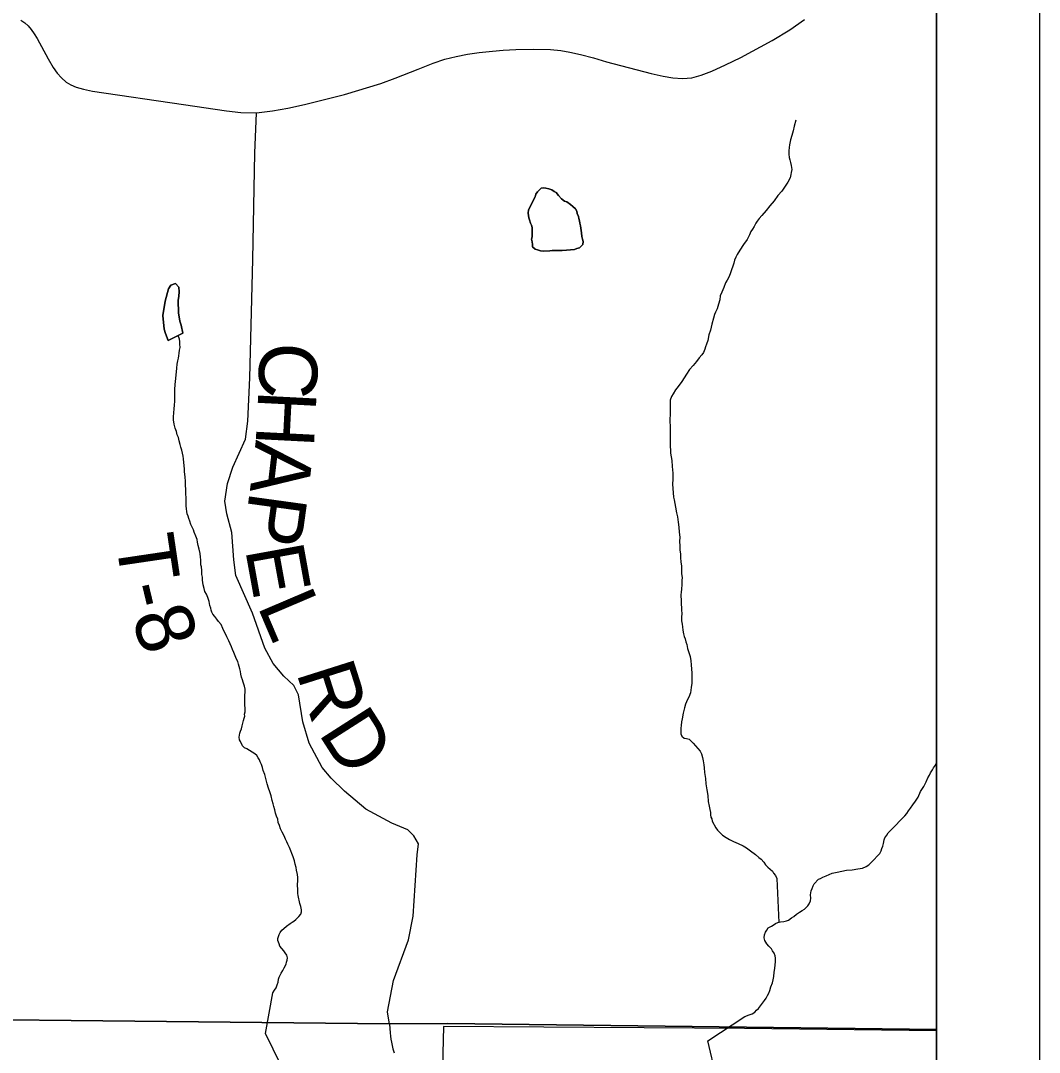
# Model space of a CAD drawing. Extents: x -14196 to 143, y -6096 to 28.
# Drawn here: x 64.011 to 65.003, y 18.706 to 19.711 of the extents above; entities that cross this region are included whole.
import ezdxf

# ---------------------------------------------------------------- set-up
doc = ezdxf.new("R2010")
doc.units = 0
for name, color, linetype in [('GM_X_Corporation', 7, 'Continuous'), ('GM_X_Minor_Lake', 7, 'Continuous'), ('GM_X_Minor_River', 7, 'Continuous'), ('GM_X_State_Route', 7, 'Continuous'), ('GM_X_Township_Road', 7, 'Continuous'), ('GM_X_Township_Road_Text', 7, 'Continuous'), ('SH_Data', 7, 'Continuous')]:
    doc.layers.add(name, color=color, linetype=linetype)

msp = doc.modelspace()

# ---------------------------------------------------------------- linework, layer by layer
at = {"layer": 'GM_X_Corporation'}
for points in [[(64.9028, 18.7286), (64.9028, 23.6985), (62.6174, 23.6985), (62.6129, 23.4358), (62.306, 23.4402), (62.2824, 22.5866), (62.2815, 22.5484), (62.2751, 22.2884), (62.2487, 21.1358), (62.2323, 20.4208), (62.2235, 19.866), (62.1999, 18.7816), (62.384, 18.775), (62.5403, 18.7731), (63.0887, 18.7577), (63.6879, 18.7414), (64.3696, 18.7343), (64.4266, 18.7347)], [(64.9028, 17.7536), (64.9028, 18.7274), (64.7157, 18.7298), (64.4224, 18.7316), (64.4198, 18.6269), (64.4192, 18.6133), (64.4194, 18.5996), (64.4162, 18.5787), (64.4151, 18.4859), (64.394, 17.7675)]]:
    msp.add_lwpolyline(points, close=True, dxfattribs=at)
for points in [[(62.5403, 18.7731), (63.0887, 18.7577), (63.6879, 18.7414), (64.3696, 18.7343), (64.4266, 18.7347), (64.9028, 18.7286), (64.9028, 23.6985)], [(58.1028, 16.8985), (64.9028, 16.8985), (64.9028, 18.7286), (64.4266, 18.7347), (64.3696, 18.7343), (63.6879, 18.7414), (63.0887, 18.7577), (62.5403, 18.7731)], [(62.3117, 16.8985), (64.9028, 16.8985), (64.9028, 18.7286), (64.4266, 18.7347), (64.3696, 18.7343), (63.6879, 18.7414), (63.0887, 18.7577), (62.5403, 18.7731)]]:
    msp.add_lwpolyline(points, dxfattribs=at)
at = {"layer": 'GM_X_Minor_Lake'}
for points in [[(64.5118, 19.5398), (64.5125, 19.5425), (64.514, 19.5448), (64.5177, 19.5483), (64.5196, 19.5487), (64.5223, 19.5484), (64.525, 19.5476), (64.528, 19.5466), (64.5303, 19.5451), (64.5322, 19.544), (64.5346, 19.5413), (64.5373, 19.538), (64.5404, 19.5357), (64.5427, 19.535), (64.5461, 19.5324), (64.5485, 19.5305), (64.5512, 19.5283), (64.5523, 19.526), (64.5528, 19.5237), (64.5539, 19.5207), (64.5544, 19.5188), (64.5548, 19.5165), (64.5552, 19.5143), (64.556, 19.5116), (64.5564, 19.5093), (64.5565, 19.507), (64.5569, 19.5048), (64.5573, 19.5013), (64.5578, 19.4987), (64.5586, 19.4964), (64.5582, 19.4934), (64.5549, 19.4903), (64.5522, 19.4895), (64.55, 19.4887), (64.5462, 19.4882), (64.5424, 19.4878), (64.5382, 19.4877), (64.534, 19.4876), (64.5306, 19.4876), (64.5283, 19.4875), (64.526, 19.4871), (64.5196, 19.487), (64.5169, 19.4873), (64.5139, 19.4881), (64.5119, 19.4888), (64.5092, 19.491), (64.5092, 19.4933), (64.5088, 19.496), (64.5083, 19.4986), (64.5087, 19.5009), (64.509, 19.504), (64.5089, 19.5078), (64.5089, 19.5101), (64.5081, 19.5123), (64.5073, 19.5142), (64.5061, 19.5176), (64.5057, 19.5195), (64.5053, 19.5218), (64.5049, 19.5241), (64.5052, 19.5271), (64.5118, 19.5398)], [(64.5582, 19.4934), (64.5586, 19.4964), (64.5578, 19.4987), (64.5573, 19.5013), (64.5569, 19.5048), (64.5565, 19.507), (64.5564, 19.5093), (64.556, 19.5116), (64.5552, 19.5143), (64.5548, 19.5165), (64.5544, 19.5188), (64.5539, 19.5207), (64.5528, 19.5237), (64.5523, 19.526), (64.5512, 19.5283), (64.5485, 19.5305), (64.5461, 19.5324), (64.5427, 19.535), (64.5404, 19.5357), (64.5373, 19.538), (64.5346, 19.5413), (64.5322, 19.544), (64.5303, 19.5451), (64.528, 19.5466), (64.525, 19.5476), (64.5223, 19.5484), (64.5196, 19.5487), (64.5177, 19.5483), (64.514, 19.5448), (64.5125, 19.5425), (64.5118, 19.5398)], [(64.5118, 19.5398), (64.5052, 19.5271), (64.5049, 19.5241), (64.5053, 19.5218), (64.5057, 19.5195), (64.5061, 19.5176), (64.5073, 19.5142), (64.5081, 19.5123), (64.5089, 19.5101), (64.5089, 19.5078), (64.509, 19.504), (64.5087, 19.5009), (64.5083, 19.4986), (64.5088, 19.496), (64.5092, 19.4933), (64.5092, 19.491), (64.5119, 19.4888), (64.5139, 19.4881), (64.5169, 19.4873), (64.5196, 19.487), (64.526, 19.4871), (64.5283, 19.4875), (64.5306, 19.4876), (64.534, 19.4876), (64.5382, 19.4877), (64.5424, 19.4878), (64.5462, 19.4882), (64.55, 19.4887), (64.5522, 19.4895), (64.5549, 19.4903), (64.5582, 19.4934)], [(64.1646, 19.4517), (64.1615, 19.4555), (64.1569, 19.4539), (64.1547, 19.4501), (64.1514, 19.4382), (64.1493, 19.4241), (64.1506, 19.4108), (64.1518, 19.4066), (64.1545, 19.4)], [(64.1545, 19.4), (64.1518, 19.4066), (64.1506, 19.4108), (64.1493, 19.4241), (64.1514, 19.4382), (64.1547, 19.4501), (64.1569, 19.4539), (64.1615, 19.4555), (64.1646, 19.4517), (64.165, 19.4472), (64.1647, 19.443), (64.164, 19.4388), (64.1645, 19.427), (64.1657, 19.4186), (64.1669, 19.4148), (64.1685, 19.4069), (64.1545, 19.4)], [(64.1545, 19.4), (64.1685, 19.4069), (64.1669, 19.4148), (64.1657, 19.4186), (64.1645, 19.427), (64.164, 19.4388), (64.1647, 19.443), (64.165, 19.4472), (64.1646, 19.4517)]]:
    msp.add_lwpolyline(points, dxfattribs=at)
at = {"layer": 'GM_X_Minor_River'}
for points in [[(64.7655, 19.6145), (64.7641, 19.6088), (64.763, 19.6042), (64.7616, 19.5996), (64.7605, 19.5954), (64.7595, 19.5904), (64.7591, 19.5878), (64.7588, 19.5847), (64.7589, 19.5813), (64.7593, 19.5782), (64.7597, 19.576), (64.7605, 19.5733), (64.761, 19.5703), (64.7618, 19.5665), (64.7611, 19.5634), (64.7607, 19.5615), (64.76, 19.5584), (64.7578, 19.5542), (64.7552, 19.5504), (64.7519, 19.5454), (64.7482, 19.5411), (64.7445, 19.5361), (64.7404, 19.5311), (64.7367, 19.5264), (64.7326, 19.5218), (64.73, 19.5187), (64.7281, 19.516), (64.7266, 19.5141), (64.7252, 19.511), (64.7233, 19.5083), (64.7218, 19.506), (64.7204, 19.5029), (64.7182, 19.4983), (64.7148, 19.4933), (64.7111, 19.4879), (64.7085, 19.4837), (64.7071, 19.481), (64.706, 19.4783), (64.7053, 19.4753), (64.702, 19.4657), (64.7006, 19.4622), (64.6987, 19.4588), (64.6972, 19.4561), (64.6954, 19.4515), (64.6936, 19.4469), (64.6921, 19.4434), (64.6915, 19.4396), (64.6904, 19.4354), (64.6889, 19.4308), (64.6875, 19.4274), (64.6864, 19.4251), (64.6853, 19.4216), (64.6839, 19.4159), (64.6825, 19.4101), (64.681, 19.4055), (64.68, 19.3998), (64.6785, 19.3964), (64.6778, 19.3937), (64.6771, 19.3914), (64.6756, 19.3883), (64.6742, 19.386), (64.6716, 19.3829), (64.669, 19.3795), (64.6656, 19.3756), (64.6622, 19.3717), (64.6593, 19.3671), (64.6545, 19.3598), (64.6511, 19.3552), (64.6485, 19.3517), (64.6463, 19.3478), (64.6445, 19.3455), (64.6434, 19.3417), (64.6431, 19.3394), (64.6431, 19.336), (64.6432, 19.3329), (64.6432, 19.3291), (64.643, 19.3219), (64.6431, 19.3154), (64.6432, 19.3082), (64.6434, 19.2994), (64.6435, 19.2903), (64.6448, 19.2831), (64.6453, 19.277), (64.6458, 19.2705), (64.6459, 19.2648), (64.6456, 19.2599), (64.6466, 19.2473), (64.647, 19.2447), (64.6478, 19.2412), (64.6483, 19.2374), (64.6495, 19.2321), (64.6504, 19.228), (64.6512, 19.223), (64.6517, 19.2181), (64.6521, 19.2131), (64.6526, 19.2082), (64.6523, 19.204), (64.6528, 19.1998), (64.6528, 19.196), (64.6533, 19.1918), (64.6533, 19.1884)], [(64.1607, 19.3409), (64.161, 19.3447), (64.1609, 19.3485), (64.1609, 19.3523), (64.1612, 19.3569), (64.1615, 19.3599), (64.1618, 19.363), (64.1622, 19.3664), (64.1625, 19.3694), (64.1628, 19.3729), (64.1631, 19.3767), (64.1638, 19.3801), (64.1645, 19.3828), (64.1649, 19.3851), (64.1652, 19.3874), (64.1655, 19.3904), (64.1659, 19.3931), (64.1658, 19.3962), (64.1658, 19.3988), (64.1653, 19.4011), (64.164, 19.4047)], [(64.2285, 19.032), (64.2289, 19.0339), (64.2288, 19.0358), (64.2292, 19.0381), (64.2295, 19.0415), (64.229, 19.045), (64.229, 19.0491), (64.2289, 19.0537), (64.2292, 19.0579), (64.2292, 19.0602), (64.2287, 19.0632), (64.2279, 19.0651), (64.2275, 19.067), (64.2267, 19.0693), (64.2259, 19.0719), (64.2251, 19.075), (64.2247, 19.0776), (64.2242, 19.0799), (64.2234, 19.0822), (64.223, 19.0845), (64.2222, 19.0871), (64.221, 19.0894), (64.2195, 19.0928), (64.2183, 19.0958), (64.2171, 19.0988), (64.2159, 19.1015), (64.2147, 19.1045), (64.2135, 19.1072), (64.2123, 19.1094), (64.2115, 19.1113), (64.2076, 19.1192), (64.206, 19.1234), (64.2033, 19.126), (64.2017, 19.1283), (64.1998, 19.1309), (64.1978, 19.1332), (64.197, 19.1354), (64.1962, 19.1373), (64.1958, 19.1392), (64.195, 19.1419), (64.1942, 19.1457), (64.193, 19.1495), (64.1918, 19.1529), (64.1902, 19.1555), (64.1894, 19.1582), (64.1886, 19.162), (64.1882, 19.1642), (64.1877, 19.1665), (64.1877, 19.1692), (64.1873, 19.1718), (64.1872, 19.176), (64.1867, 19.1794), (64.1863, 19.1813), (64.1863, 19.1844), (64.1862, 19.1863), (64.1858, 19.1889), (64.1854, 19.1924), (64.1845, 19.1965), (64.1837, 19.2003), (64.1829, 19.2034), (64.1825, 19.206), (64.1813, 19.2094), (64.1797, 19.2132), (64.1789, 19.2155), (64.1777, 19.2181), (64.1765, 19.2208), (64.1753, 19.2238), (64.1745, 19.2265), (64.1737, 19.2287), (64.1729, 19.231), (64.1725, 19.2333), (64.1721, 19.2359), (64.172, 19.239), (64.172, 19.242), (64.1714, 19.255), (64.1713, 19.2588), (64.1712, 19.263), (64.1708, 19.2668), (64.1707, 19.2698), (64.1703, 19.2721), (64.1702, 19.2744), (64.1698, 19.2782), (64.1697, 19.2812), (64.1693, 19.2846), (64.1689, 19.2873), (64.1684, 19.29), (64.1676, 19.293), (64.1668, 19.296), (64.166, 19.2987), (64.1652, 19.3021), (64.1644, 19.3055), (64.1632, 19.3081), (64.1624, 19.3112), (64.1612, 19.3146), (64.1603, 19.3184), (64.1595, 19.3226), (64.1595, 19.3256), (64.1598, 19.3294), (64.1601, 19.3332), (64.1604, 19.337), (64.1607, 19.3409)], [(64.6533, 19.1884), (64.6538, 19.1838), (64.6542, 19.1804), (64.6543, 19.1766), (64.6544, 19.1728), (64.6548, 19.1686), (64.6545, 19.1663), (64.6545, 19.1644), (64.6546, 19.1618), (64.6543, 19.158), (64.6539, 19.1545), (64.6536, 19.1526), (64.6536, 19.1503), (64.6541, 19.148), (64.6541, 19.1446), (64.6542, 19.1378), (64.6547, 19.1332), (64.6544, 19.1309), (64.6544, 19.1267), (64.6549, 19.1237), (64.6553, 19.121), (64.6557, 19.1176), (64.6562, 19.1142), (64.657, 19.1115), (64.6578, 19.1093), (64.6586, 19.1062), (64.6594, 19.1036), (64.6602, 19.0998), (64.6614, 19.096), (64.6626, 19.0922), (64.6635, 19.0877), (64.6636, 19.0838), (64.664, 19.0797), (64.6644, 19.0762), (64.6642, 19.066), (64.6636, 19.0618), (64.6629, 19.0568), (64.6614, 19.0526), (64.6603, 19.0503), (64.6592, 19.048), (64.6581, 19.0457), (64.6571, 19.0422), (64.656, 19.0369), (64.655, 19.0315), (64.6543, 19.0285), (64.654, 19.025), (64.6536, 19.0224), (64.6537, 19.0205), (64.6537, 19.0167), (64.6545, 19.0144), (64.6568, 19.0125), (64.6591, 19.0122), (64.6618, 19.0115), (64.6657, 19.0077), (64.668, 19.0051), (64.6703, 19.0025), (64.6726, 18.9998), (64.6738, 18.9972), (64.6746, 18.9938), (64.6755, 18.9904), (64.6759, 18.9866), (64.6764, 18.9835), (64.6768, 18.979), (64.6777, 18.9733), (64.6781, 18.968), (64.679, 18.9623), (64.6799, 18.9566), (64.6804, 18.9509), (64.6812, 18.9463), (64.682, 18.9429), (64.6824, 18.9402), (64.6825, 18.9379), (64.6829, 18.9357), (64.6837, 18.9338), (64.6841, 18.9315), (64.6877, 18.9251), (64.6892, 18.9228), (64.6915, 18.9206), (64.6942, 18.918), (64.6977, 18.9157), (64.7012, 18.9139), (64.705, 18.912), (64.7096, 18.9098), (64.7142, 18.9076), (64.7176, 18.9058), (64.7215, 18.9028), (64.7265, 18.8991), (64.7296, 18.8961), (64.7319, 18.8946), (64.7346, 18.8916), (64.7362, 18.889), (64.7385, 18.8867), (64.7408, 18.8849), (64.7428, 18.883), (64.7439, 18.8811), (64.7459, 18.8788), (64.7471, 18.8758), (64.7492, 18.8331)], [(64.249, 18.7248), (64.2564, 18.7644), (64.2579, 18.7671), (64.2594, 18.7694), (64.2605, 18.7721), (64.2616, 18.7748), (64.2619, 18.7778), (64.2626, 18.7797), (64.2645, 18.7836), (64.2659, 18.7863), (64.2674, 18.7889), (64.2693, 18.7924), (64.2696, 18.7943), (64.2703, 18.7962), (64.2707, 18.7985), (64.2699, 18.8012), (64.2683, 18.8034), (64.2671, 18.8053), (64.2652, 18.8076), (64.2632, 18.8098), (64.2624, 18.8121), (64.2612, 18.8155), (64.2612, 18.8174), (64.2623, 18.8212), (64.2634, 18.8232), (64.2652, 18.8255), (64.2671, 18.827), (64.2697, 18.8294), (64.2731, 18.8321), (64.275, 18.8332), (64.2769, 18.8344), (64.2787, 18.836), (64.2817, 18.8387), (64.2836, 18.841), (64.2843, 18.8433), (64.2843, 18.8452), (64.2835, 18.8486), (64.2827, 18.8513), (64.281, 18.8592), (64.2806, 18.8611), (64.2805, 18.8638), (64.2805, 18.8661), (64.2804, 18.8684), (64.2804, 18.8707), (64.2807, 18.8729), (64.2807, 18.8748), (64.2807, 18.8768), (64.2802, 18.8798), (64.2794, 18.884), (64.279, 18.8866), (64.2782, 18.8897), (64.2773, 18.8931), (64.2761, 18.8969), (64.2749, 18.9003), (64.2738, 18.9029), (64.2726, 18.9059), (64.271, 18.9093), (64.2698, 18.9116), (64.2686, 18.9142), (64.2674, 18.9173), (64.2654, 18.921), (64.2639, 18.9241), (64.2627, 18.9275), (64.2615, 18.9305), (64.261, 18.9335), (64.2599, 18.9366), (64.259, 18.9396), (64.2582, 18.9426), (64.2574, 18.946), (64.2566, 18.9487), (64.2558, 18.9517), (64.2546, 18.9563), (64.2534, 18.9601), (64.2521, 18.9639), (64.2509, 18.968), (64.2497, 18.9718), (64.2485, 18.9771), (64.2469, 18.9809), (64.2461, 18.9839), (64.2453, 18.987), (64.2441, 18.9896), (64.2433, 18.9915), (64.2421, 18.9934), (64.2406, 18.9956), (64.2386, 18.9971), (64.2309, 19.002), (64.2286, 19.0031), (64.2267, 19.0049), (64.2247, 19.0091), (64.2239, 19.011), (64.2235, 19.0136), (64.2242, 19.0175), (64.2249, 19.0194), (64.2257, 19.0217), (64.2264, 19.0244), (64.2271, 19.027), (64.2278, 19.0297), (64.2285, 19.032)], [(64.8958, 18.9766), (64.8969, 18.9789), (64.8987, 18.9816), (64.8998, 18.9835), (64.9017, 18.9862), (64.9028, 18.9877)], [(64.6798, 18.7178), (64.716, 18.7413), (64.7202, 18.7429), (64.7232, 18.7441), (64.7258, 18.7456), (64.7273, 18.7475), (64.7292, 18.7491), (64.7321, 18.753), (64.7351, 18.7568), (64.7366, 18.7591), (64.7381, 18.7618), (64.7392, 18.7641), (64.7403, 18.7668), (64.7413, 18.7702), (64.7428, 18.7741), (64.7435, 18.7771), (64.7442, 18.7802), (64.7445, 18.7844), (64.7452, 18.7882), (64.7458, 18.7951), (64.7458, 18.7981), (64.7454, 18.8004), (64.7445, 18.803), (64.743, 18.8053), (64.7418, 18.8072), (64.7395, 18.8098), (64.7375, 18.8121), (64.7356, 18.8155), (64.7348, 18.8181), (64.7351, 18.8208), (64.7362, 18.8235), (64.7373, 18.8254), (64.7388, 18.8277), (64.7418, 18.8293), (64.7437, 18.8304), (64.7459, 18.832), (64.7482, 18.8328), (64.7508, 18.8336), (64.7539, 18.834), (64.7565, 18.8345), (64.7584, 18.8353), (64.7614, 18.8376), (64.7637, 18.8388), (64.7663, 18.8411), (64.7693, 18.8431), (64.7719, 18.8446), (64.7742, 18.8458), (64.7772, 18.8493), (64.7787, 18.8512), (64.7798, 18.8539), (64.7801, 18.8566), (64.78, 18.86), (64.7804, 18.8619), (64.7807, 18.8638), (64.7814, 18.8661), (64.7825, 18.8688), (64.7836, 18.8707), (64.7877, 18.875), (64.7896, 18.8758), (64.7919, 18.877), (64.7953, 18.8785), (64.8009, 18.8809), (64.8059, 18.8821), (64.8104, 18.883), (64.815, 18.8838), (64.8206, 18.8843), (64.826, 18.8851), (64.8305, 18.886), (64.8343, 18.8876), (64.8369, 18.8891), (64.8388, 18.8911), (64.8418, 18.8942), (64.8447, 18.8976), (64.8473, 18.9003), (64.8488, 18.9027), (64.8495, 18.905), (64.8503, 18.9072), (64.851, 18.9099), (64.8517, 18.9134), (64.8524, 18.9153), (64.8543, 18.918), (64.8557, 18.9203), (64.8598, 18.9245), (64.8632, 18.928), (64.8666, 18.9315), (64.8695, 18.9346), (64.8718, 18.9369), (64.8736, 18.9392), (64.8755, 18.9416), (64.8774, 18.9443), (64.8796, 18.9477), (64.8822, 18.9512), (64.8848, 18.955), (64.887, 18.9604), (64.8903, 18.9654), (64.8925, 18.97), (64.8943, 18.9739), (64.8958, 18.9766)], [(64.2715, 18.6789), (64.249, 18.7248)], [(64.6882, 18.6832), (64.6798, 18.7178)]]:
    msp.add_lwpolyline(points, dxfattribs=at)
at = {"layer": 'GM_X_State_Route'}
msp.add_lwpolyline([(64.0108, 19.7119), (64.0146, 19.7094), (64.018, 19.7065), (64.021, 19.7029), (64.024, 19.6986), (64.0267, 19.6942), (64.0376, 19.6743), (64.0423, 19.666), (64.0464, 19.6602), (64.0504, 19.6557), (64.0551, 19.6517), (64.0596, 19.6488), (64.0647, 19.6466), (64.0719, 19.6446), (64.0806, 19.6429), (64.1693, 19.6298), (64.2112, 19.6235), (64.225, 19.6221), (64.2405, 19.6218), (64.2559, 19.6236), (64.271, 19.6262), (64.287, 19.6297), (64.3261, 19.6396), (64.3616, 19.6504), (64.3755, 19.6553), (64.3979, 19.6641), (64.4126, 19.67), (64.4237, 19.6739), (64.4348, 19.6767), (64.4459, 19.6787), (64.4574, 19.6803), (64.4703, 19.6819), (64.4807, 19.6827), (64.493, 19.6834), (64.5102, 19.6838), (64.5267, 19.6835), (64.5367, 19.6824), (64.5456, 19.6809), (64.5558, 19.6786), (64.5687, 19.6751), (64.5814, 19.6714), (64.6248, 19.66), (64.6366, 19.6574), (64.646, 19.6557), (64.6553, 19.6552), (64.6642, 19.6559), (64.6733, 19.6585), (64.6837, 19.6624), (64.6972, 19.6684), (64.7121, 19.6757), (64.7425, 19.692), (64.7599, 19.7026), (64.774, 19.7125)], dxfattribs=at)
at = {"layer": 'GM_X_Township_Road'}
for points in [[(64.3698, 18.7338), (64.3681, 18.7459), (64.3738, 18.7764), (64.3885, 18.816), (64.393, 18.8392), (64.397, 18.899), (64.398, 18.9096), (64.3937, 18.9175), (64.3877, 18.9232), (64.3722, 18.9298), (64.347, 18.9433), (64.3262, 18.9609), (64.313, 18.9734), (64.3044, 18.984), (64.2918, 19.0078), (64.2856, 19.0283), (64.2812, 19.0548), (64.2769, 19.0637), (64.267, 19.073), (64.2567, 19.0852), (64.2485, 19.1001), (64.2366, 19.1342), (64.2201, 19.1709), (64.2184, 19.1861), (64.2164, 19.2129), (64.2114, 19.2311), (64.2097, 19.2435), (64.2121, 19.2606), (64.2174, 19.2764), (64.2296, 19.3039), (64.2319, 19.3214), (64.2339, 19.3634), (64.2369, 19.4789), (64.2387, 19.5824), (64.2405, 19.6218)], [(64.3698, 18.7338), (64.3701, 18.7297), (64.3705, 18.7254), (64.3709, 18.7222), (64.3713, 18.7193), (64.3718, 18.7163), (64.3725, 18.7132), (64.3733, 18.7098), (64.3745, 18.706)]]:
    msp.add_lwpolyline(points, dxfattribs=at)
at = {"layer": 'SH_Data'}
for p, q in [((65.0028, 23.7985), (65.0028, 16.7985)), ((64.9028, 23.6985), (64.9028, 16.8985))]:
    msp.add_line(p, q, dxfattribs=at)

# ---------------------------------------------------------------- texts
at = {"layer": 'GM_X_Township_Road_Text'}
for s, rotation, p in [('C', 268.0716, (64.2438, 19.3988)), ('H', 267.0699, (64.2423, 19.3525)), ('A', 263.3223, (64.2398, 19.3035)), ('P', 262.14, (64.234, 19.2542)), ('T', 278.4344, (64.103, 19.2069)), ('E', 280.295, (64.2292, 19.1966)), ('-', 283.4796, (64.1102, 19.1595)), ('L', 293.0914, (64.2408, 19.1416)), ('8', 289.9134, (64.1177, 19.1302)), ('R', 287.5808, (64.2789, 19.0768)), ('D', 302.6123, (64.2999, 19.0176))]:
    msp.add_text(s, height=0.0568, rotation=rotation, dxfattribs=at).set_placement(p)

doc.saveas('drawing.dxf')
